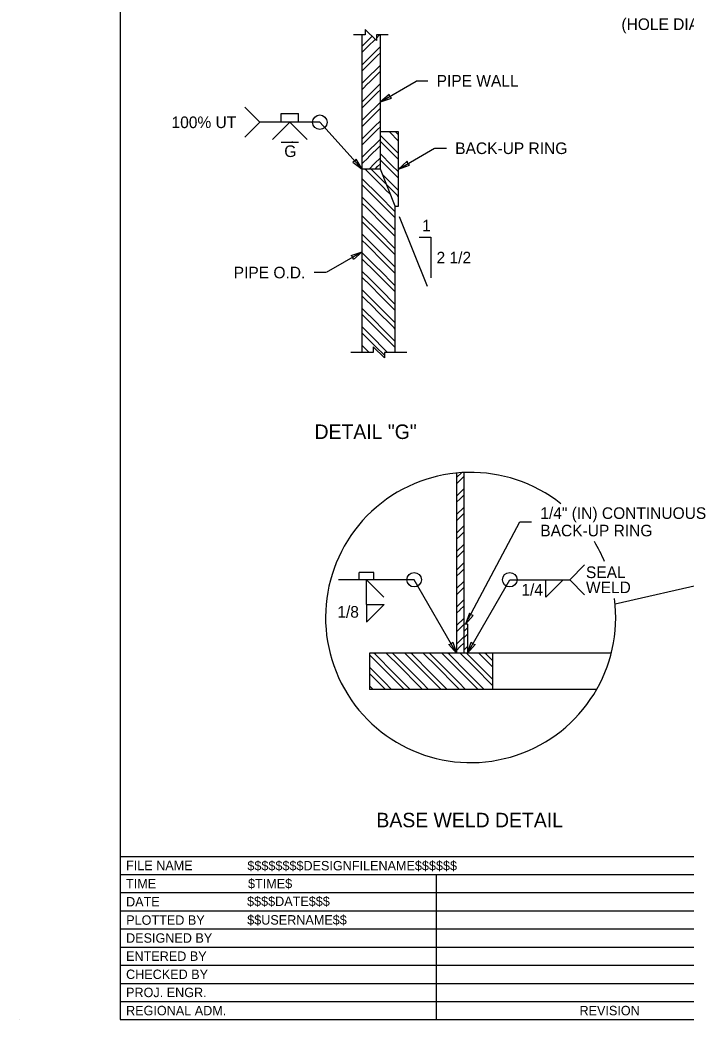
# Model space of a CAD drawing. Extents: x 99862 to 104211, y 98939 to 111076.
# Drawn here: x 99862 to 100780, y 109000 to 110378 of the extents above; entities that cross this region are included whole.
import ezdxf

# ---------------------------------------------------------------- set-up
doc = ezdxf.new("R2010")
doc.units = 0
for name, color, linetype in [('Level 10', 7, 'Continuous'), ('Level 11', 7, 'Continuous'), ('Level 15', 7, 'Continuous'), ('Level 2', 7, 'Continuous'), ('Level 20', 7, 'Continuous'), ('Level 3', 7, 'Continuous'), ('Level 60', 7, 'Continuous')]:
    doc.layers.add(name, color=color, linetype=linetype)

msp = doc.modelspace()

# ---------------------------------------------------------------- linework, layer by layer
at = {"layer": 'Level 10'}
msp.add_line((100246, 110208.9), (100222, 110208.9), dxfattribs=at)
at = {"layer": 'Level 11'}
for p, q in [((100463.7, 109747), (100470.5, 109753.8)), ((100463.7, 109738.5), (100473.7, 109748.5)), ((100464.4, 109722.2), (100473.7, 109731.5)), ((100463.7, 109721.5), (100464.4, 109722.2)), ((100463.7, 109713), (100468.7, 109718)), ((100468.7, 109718), (100473.7, 109723)), ((100463.7, 109696), (100473.7, 109706)), ((100463.7, 109687.5), (100473.7, 109697.5)), ((100463.7, 109670.5), (100464.4, 109671.2)), ((100464.5, 109671.3), (100473.7, 109680.5)), ((100468.7, 109667), (100473.7, 109672)), ((100473.7, 109673), (100473.7, 109673)), ((100463.7, 109662), (100468.7, 109667)), ((100463.7, 109645), (100473.7, 109655)), ((100463.7, 109636.5), (100473.7, 109646.5)), ((100464.5, 109620.3), (100473.7, 109629.5)), ((100463.7, 109619.5), (100464.5, 109620.3)), ((100463.7, 109611), (100468.7, 109616)), ((100468.7, 109616), (100473.7, 109621)), ((100463.7, 109594), (100473.7, 109604)), ((100463.7, 109585.5), (100473.7, 109595.5)), ((100464.5, 109569.3), (100473.7, 109578.5)), ((100463.7, 109568.5), (100464.5, 109569.3)), ((100463.7, 109560), (100468.7, 109565)), ((100468.7, 109565.1), (100473.7, 109570)), ((100463.7, 109543), (100473.7, 109553)), ((100463.7, 109534.5), (100473.7, 109544.5)), ((100473.7, 109534.9), (100478.7, 109539.9)), ((100476.4, 109529.1), (100478.7, 109531.4)), ((100463.7, 109517.5), (100464.5, 109518.3)), ((100464.5, 109518.3), (100473.7, 109527.5)), ((100468.8, 109514.1), (100473.7, 109519)), ((100473.7, 109526.4), (100476.4, 109529.1)), ((100351.8, 109503.1), (100349.8, 109505.1)), ((100385.8, 109486.1), (100366.9, 109505.1)), ((100390.1, 109490.4), (100375.3, 109505.1)), ((100398.6, 109498.9), (100392.4, 109505.1)), ((100402.8, 109503.1), (100400.8, 109505.1)), ((100436.8, 109486.2), (100417.9, 109505.1)), ((100441.1, 109490.4), (100426.3, 109505.1)), ((100449.6, 109498.9), (100443.4, 109505.1)), ((100453.8, 109503.2), (100451.8, 109505.1)), ((100463.7, 109509), (100468.7, 109514.1)), ((100487.8, 109486.2), (100468.9, 109505.1)), ((100473.7, 109509.4), (100478.7, 109514.4)), ((100492, 109490.4), (100477.3, 109505.1)), ((100500.5, 109498.9), (100494.4, 109505.1)), ((100504.8, 109503.2), (100502.8, 109505.1)), ((100677.1, 109505.1), (100513.7, 109505.1)), ((100347.6, 109498.9), (100343.7, 109502.8)), ((100373.1, 109473.4), (100347.6, 109498.9)), ((100377.3, 109477.6), (100351.9, 109503.1)), ((100415.6, 109464.9), (100390.1, 109490.4)), ((100424.1, 109473.4), (100398.6, 109498.9)), ((100428.3, 109477.7), (100402.8, 109503.1)), ((100466.5, 109464.9), (100441.1, 109490.4)), ((100475, 109473.4), (100449.6, 109498.9)), ((100479.3, 109477.7), (100453.8, 109503.1)), ((100513.7, 109468.8), (100492.1, 109490.4)), ((100513.7, 109485.8), (100500.6, 109498.9)), ((100513.7, 109494.3), (100504.8, 109503.2)), ((100364.6, 109464.9), (100343.7, 109485.8)), ((100360.3, 109460.6), (100343.7, 109477.3)), ((100399.8, 109455.1), (100377.3, 109477.6)), ((100411.3, 109460.7), (100385.9, 109486.1)), ((100450.8, 109455.1), (100428.3, 109477.6)), ((100462.3, 109460.7), (100436.8, 109486.1)), ((100501.8, 109455.1), (100479.3, 109477.7)), ((100513.3, 109460.7), (100487.8, 109486.2)), ((100374.3, 109455.1), (100364.6, 109464.9)), ((100391.4, 109455.1), (100373.1, 109473.4)), ((100425.3, 109455.1), (100415.6, 109464.9)), ((100442.4, 109455.1), (100424.1, 109473.4)), ((100476.3, 109455.1), (100466.6, 109464.9)), ((100493.4, 109455.1), (100475.1, 109473.4)), ((100348.8, 109455.1), (100343.7, 109460.3)), ((100365.9, 109455.1), (100360.4, 109460.6)), ((100416.9, 109455.1), (100411.3, 109460.6)), ((100467.9, 109455.1), (100462.3, 109460.7)), ((100513.7, 109460.3), (100513.3, 109460.7)), ((100656.9, 109455.1), (100513.7, 109455.1))]:
    msp.add_line(p, q, dxfattribs=at)
at = {"layer": 'Level 15'}
for p, q in [((100358.8, 110264.8), (100408.3, 110293.4)), ((100408.3, 110294), (100424.3, 110294)), ((100172.1, 110257.5), (100192.7, 110236.9)), ((100222, 110248.9), (100246, 110248.9)), ((100222, 110236.9), (100222, 110248.9)), ((100246, 110236.9), (100246, 110248.9)), ((100172.1, 110216.3), (100192.7, 110236.9)), ((100275.3, 110236.9), (100192.7, 110236.9)), ((100210, 110212.9), (100234, 110236.9)), ((100258, 110212.9), (100234, 110236.9)), ((100333.8, 110172.4), (100275.3, 110236.9)), ((100383.8, 110172.4), (100433.3, 110201)), ((100433.9, 110201), (100449.9, 110201)), ((100423.6, 110010.4), (100385.2, 110106.4)), ((100412.4, 110078.4), (100428.4, 110078.4)), ((100428.4, 110078.4), (100428.4, 110022.3)), ((100333.8, 110058.3), (100284.2, 110029.7)), ((100283.6, 110029.7), (100267.6, 110029.7)), ((100476.2, 109545.1), (100551.2, 109686.1)), ((100551.2, 109686.1), (100567.2, 109686.1)), ((100989.6, 109643.1), (100682.4, 109572.5)), ((100329.7, 109606.3), (100329.7, 109616.3)), ((100349.7, 109616.3), (100329.7, 109616.3)), ((100349.7, 109606.3), (100349.7, 109616.3)), ((100640.3, 109626.9), (100619.7, 109606.3)), ((100339.7, 109606.3), (100301.2, 109606.3)), ((100405.3, 109606.3), (100339.7, 109606.3)), ((100339.7, 109572.1), (100339.7, 109606.3)), ((100363.7, 109582.1), (100339.7, 109606.1)), ((100463.7, 109505.1), (100405.3, 109606.3)), ((100478.7, 109505.1), (100537.1, 109606.3)), ((100537.1, 109606.3), (100619.7, 109606.3)), ((100586.8, 109582.3), (100610.8, 109606.3)), ((100586.8, 109582.3), (100586.8, 109606.3)), ((100640.3, 109585.7), (100619.7, 109606.3)), ((100339.7, 109572.1), (100339.7, 109548.1)), ((100363.9, 109572.1), (100339.7, 109547.9)), ((100339.7, 109572.1), (100363.9, 109572.1))]:
    msp.add_line(p, q, dxfattribs=at)
for points in [[(100369.4, 110357.2), (100353.4, 110357.2), (100353.4, 110349.4), (100337.9, 110364.9), (100337.9, 110357.2), (100321.9, 110357.2)], [(100395.2, 109919.7), (100364.2, 109919.7), (100364.2, 109912), (100348.7, 109927.4), (100348.7, 109919.7), (100317.8, 109919.7)]]:
    msp.add_lwpolyline(points, dxfattribs=at)
for points in [[(100358.8, 110264.8), (100373.9, 110270), (100371.7, 110272.3), (100370.8, 110275.3)], [(100333.8, 110172.4), (100325.4, 110186.1), (100323.7, 110183.5), (100320.9, 110182)], [(100383.8, 110172.4), (100398.9, 110177.6), (100396.8, 110179.9), (100395.8, 110183)], [(100333.8, 110058.3), (100321.7, 110047.8), (100320.8, 110050.8), (100318.6, 110053.1)], [(100476.2, 109545.1), (100486.7, 109557.2), (100483.7, 109558.1), (100481.4, 109560.3)], [(100463.7, 109505.1), (100453.2, 109517.2), (100456.2, 109518.1), (100458.5, 109520.3)], [(100478.7, 109505.1), (100483.9, 109520.3), (100486.2, 109518.1), (100489.2, 109517.2)]]:
    msp.add_lwpolyline(points, close=True, dxfattribs=at)
for centre in [(100275.3, 110236.9), (100405.3, 109606.3), (100537.1, 109606.3)]:
    msp.add_circle(centre, 10, dxfattribs=at)
for start, end in [(51.538, 7.4642), (22.7202, 31.4983)]:
    msp.add_arc((100483.2, 109554.3), 200, start, end, dxfattribs=at)
at = {"layer": 'Level 2'}
for p, q in [((100343.7, 109505.1), (100343.7, 109455.1)), ((100513.7, 109505.1), (100343.7, 109505.1)), ((100513.7, 109455.1), (100513.7, 109505.1)), ((100513.7, 109455.1), (100343.7, 109455.1))]:
    msp.add_line(p, q, dxfattribs=at)
at = {"layer": 'Level 3'}
for p, q in [((100333.8, 109919.7), (100333.8, 110357.2)), ((100333.8, 110341.8), (100337.8, 110345.8)), ((100337.9, 110345.9), (100347.4, 110355.4)), ((100342.1, 110341.6), (100351.6, 110351.1)), ((100353.4, 110352.9), (100357.6, 110357.2)), ((100358.8, 110172.4), (100358.8, 110357.2)), ((100333.8, 110333.3), (100342.1, 110341.6)), ((100333.8, 110316.2), (100350.6, 110333.1)), ((100350.6, 110333.1), (100358.8, 110341.2)), ((100354.9, 110328.9), (100358.8, 110332.7)), ((100333.8, 110307.7), (100354.8, 110328.8)), ((100337.9, 110294.8), (100358.8, 110315.7)), ((100342.2, 110290.6), (100358.8, 110307.2)), ((100333.8, 110290.7), (100337.9, 110294.8)), ((100333.8, 110282.2), (100342.1, 110290.5)), ((100350.7, 110282.1), (100358.8, 110290.1)), ((100333.8, 110265.1), (100350.6, 110282)), ((100333.8, 110256.7), (100354.9, 110277.8)), ((100354.9, 110277.8), (100358.8, 110281.7)), ((100338, 110243.8), (100358.8, 110264.6)), ((100342.2, 110239.5), (100358.8, 110256.1)), ((100333.8, 110239.6), (100337.9, 110243.7)), ((100333.8, 110231.1), (100342.2, 110239.5)), ((100350.7, 110231), (100358.8, 110239)), ((100333.8, 110214), (100350.7, 110231)), ((100333.8, 110205.6), (100354.9, 110226.7)), ((100355, 110226.8), (100358.8, 110230.6)), ((100383.8, 110223.5), (100358.8, 110223.5)), ((100383.8, 110210.9), (100371.1, 110223.5)), ((100383.8, 110219.3), (100379.6, 110223.5)), ((100383.8, 110121.3), (100383.8, 110223.5)), ((100236.7, 110209.2), (100237.7, 110210.2)), ((100338, 110192.7), (100358.8, 110213.5)), ((100361.4, 110216.2), (100358.8, 110218.8)), ((100382.6, 110186.5), (100358.8, 110210.3)), ((100383.8, 110193.8), (100361.4, 110216.2)), ((100333.8, 110188.5), (100338, 110192.7)), ((100342.2, 110188.5), (100358.8, 110205)), ((100374.1, 110177.9), (100358.8, 110193.3)), ((100333.8, 110180), (100342.2, 110188.4)), ((100343.2, 110172.4), (100350.7, 110179.9)), ((100350.8, 110180), (100358.8, 110188)), ((100355, 110175.7), (100358.8, 110179.5)), ((100369.8, 110173.7), (100358.8, 110184.8)), ((100383.8, 110185.3), (100382.7, 110186.4)), ((100358.8, 110172.4), (100333.8, 110172.4)), ((100339.5, 110170.4), (100337.4, 110172.4)), ((100365, 110144.9), (100339.5, 110170.3)), ((100367.3, 110151), (100345.9, 110172.4)), ((100351.7, 110172.4), (100355, 110175.7)), ((100379.2, 110121.3), (100358.8, 110172.4)), ((100383.8, 110159.8), (100369.9, 110173.7)), ((100383.8, 110168.3), (100374.1, 110177.9)), ((100356.4, 110136.3), (100333.8, 110159)), ((100383.8, 110142.7), (100361.9, 110164.6)), ((100352.2, 110132.1), (100333.8, 110150.5)), ((100373, 110136.8), (100365, 110144.8)), ((100382.6, 110135.4), (100367.6, 110150.4)), ((100343.7, 110123.6), (100333.8, 110133.5)), ((100339.4, 110119.3), (100333.8, 110125)), ((100377.7, 110106.6), (100352.2, 110132.1)), ((100379.2, 110113.6), (100356.5, 110136.3)), ((100383.8, 110134.2), (100382.6, 110135.4)), ((100364.9, 110093.8), (100339.5, 110119.3)), ((100369.2, 110098.1), (100343.7, 110123.5)), ((100379.6, 110121.3), (100378.9, 110122)), ((100379.2, 109919.7), (100379.2, 110121.3)), ((100379.2, 110121.3), (100383.8, 110121.3)), ((100356.4, 110085.3), (100333.8, 110107.9)), ((100352.1, 110081.1), (100333.8, 110099.4)), ((100379.2, 110088), (100369.2, 110098)), ((100379.2, 110105.1), (100377.7, 110106.6)), ((100379.2, 110062.5), (100356.4, 110085.3)), ((100379.2, 110079.5), (100365, 110093.8)), ((100343.6, 110072.5), (100333.8, 110082.4)), ((100339.4, 110068.3), (100333.8, 110073.9)), ((100369.1, 110047), (100343.7, 110072.5)), ((100377.6, 110055.6), (100352.2, 110081)), ((100356.3, 110034.3), (100333.8, 110056.8)), ((100364.9, 110042.8), (100339.4, 110068.2)), ((100379.2, 110054), (100377.7, 110055.5)), ((100352.1, 110030), (100333.8, 110048.3)), ((100379.2, 110028.4), (100364.9, 110042.7)), ((100379.2, 110036.9), (100369.2, 110047)), ((100343.6, 110021.5), (100333.8, 110031.3)), ((100377.6, 110004.5), (100352.1, 110030)), ((100379.2, 110011.4), (100356.4, 110034.2)), ((100339.3, 110017.2), (100333.8, 110022.8)), ((100364.8, 109991.7), (100339.4, 110017.2)), ((100369.1, 109996), (100343.6, 110021.4)), ((100356.3, 109983.2), (100333.8, 110005.7)), ((100379.2, 110002.9), (100377.6, 110004.5)), ((100352.1, 109979), (100333.8, 109997.3)), ((100379.2, 109977.4), (100364.9, 109991.7)), ((100379.2, 109985.8), (100369.1, 109995.9)), ((100343.5, 109970.4), (100333.8, 109980.2)), ((100377.6, 109953.5), (100352.1, 109978.9)), ((100379.2, 109960.3), (100356.3, 109983.2)), ((100339.3, 109966.2), (100333.8, 109971.7)), ((100364.8, 109940.7), (100339.3, 109966.2)), ((100369, 109944.9), (100343.6, 109970.4)), ((100356.3, 109932.2), (100333.8, 109954.7)), ((100352, 109927.9), (100333.8, 109946.2)), ((100379.2, 109934.8), (100369.1, 109944.9)), ((100379.2, 109951.8), (100377.6, 109953.4)), ((100368.7, 109919.7), (100356.3, 109932.1)), ((100379.2, 109926.3), (100364.8, 109940.7)), ((100343.2, 109919.7), (100333.8, 109929.1)), ((100334.7, 109919.7), (100333.8, 109920.6)), ((100364.2, 109915.7), (100352.1, 109927.9)), ((100463.7, 109753.3), (100463.7, 109505.1)), ((100473.7, 109754), (100473.7, 109505.1)), ((100478.7, 109545.1), (100473.7, 109545.1)), ((100478.7, 109545.1), (100478.7, 109505.1))]:
    msp.add_line(p, q, dxfattribs=at)
at = {"layer": 'Level 60'}
for p, q in [((100000, 111075), (100000, 109000)), ((100000, 109225), (103150, 109225)), ((100000, 109200), (101490.1, 109200)), ((100435.5, 109200), (100435.5, 109000)), ((100000, 109175), (100436.1, 109175)), ((100436.1, 109175), (101088.5, 109175)), ((100000, 109150), (100436.1, 109150)), ((100436.1, 109150), (101088.5, 109150)), ((100000, 109125), (101088.5, 109125)), ((100000, 109100), (101088.5, 109100)), ((100000, 109075), (101088.5, 109075)), ((100000, 109050), (101088.5, 109050)), ((100000, 109025), (101088.5, 109025)), ((99862, 108999.5), (99862, 108999.5)), ((100000, 109000), (103150, 109000))]:
    msp.add_line(p, q, dxfattribs=at)

# ---------------------------------------------------------------- texts
at = {"layer": 'Level 10'}
for s, p in [('G', (100226.3, 110188.9)), ('1/8', (100299.4, 109554))]:
    msp.add_text(s, height=16, rotation=360, dxfattribs=at).set_placement(p)
msp.add_text('1/4', height=16, dxfattribs=at).set_placement((100553.1, 109584.5))
at = {"layer": 'Level 20'}
for s, height, p in [('(HOLE DIAM. = POST I.D. - 2" (IN))', 16, (100691, 110364)), ('PIPE WALL', 16, (100436.3, 110286)), ('100% UT', 16, (100070.9, 110228.8)), ('BACK-UP RING', 16, (100461.9, 110193)), ('1', 16, (100416.3, 110086.4)), ('2 1/2', 16, (100436.2, 110042.3)), ('PIPE O.D.', 16, (100156.6, 110021.7)), ('DETAIL "G"', 20, (100268, 109800.3)), ('1/4" (IN) CONTINUOUS ', 16, (100579.2, 109690.1)), ('BACK-UP RING', 16, (100579.2, 109666.1)), ('SEAL', 16, (100642.1, 109608.6)), ('WELD', 16, (100642.1, 109587.8)), ('BASE WELD DETAIL', 20, (100353.3, 109265.1))]:
    msp.add_text(s, height=height, dxfattribs=at).set_placement(p)
at = {"layer": 'Level 60'}
for s, p in [('FILE NAME', (100008.2, 109206)), ('$$$$$$$$DESIGNFILENAME$$$$$$', (100175.4, 109205.7)), ('TIME', (100008.2, 109181)), ('$TIME$', (100176.3, 109181)), ('DATE', (100008.2, 109156)), ('$$$$DATE$$$', (100175, 109156.6)), ('PLOTTED BY', (100008.4, 109130.7)), ('$$USERNAME$$', (100175.2, 109131)), ('DESIGNED BY', (100008.2, 109106)), ('ENTERED BY', (100008.2, 109081)), ('CHECKED BY', (100008.2, 109056)), ('PROJ. ENGR.', (100008.2, 109031)), ('REGIONAL ADM.', (100008.2, 109006)), ('REVISION', (100633.2, 109006))]:
    msp.add_text(s, height=13, dxfattribs=at).set_placement(p)

doc.saveas('drawing.dxf')
